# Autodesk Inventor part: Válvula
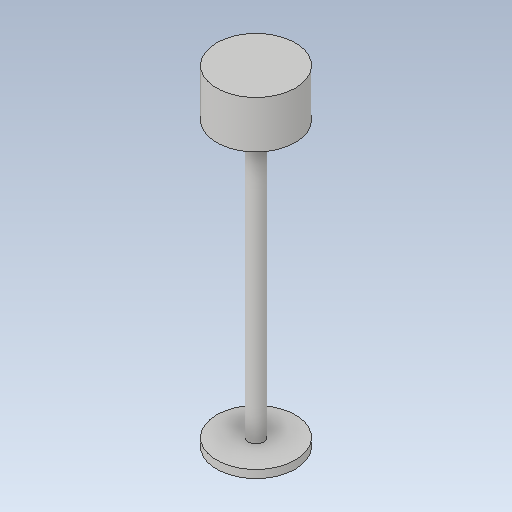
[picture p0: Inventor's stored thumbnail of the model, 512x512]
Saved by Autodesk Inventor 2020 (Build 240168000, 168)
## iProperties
Created: 2019-09
Part Number: Válvula
Material: Generic
Document SubType Name: Modeling
Designer: user
Density: 1 g/cm^3
Appearance: Default
Mass: 0.357356 g
Surface Area: 9.20487 cm^2
Volume: 0.357356 cm^3
Author: user
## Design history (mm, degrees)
sketch "Sketch1"
  geometry: C1 r 5 at (0, 0); 1 further point
  constraints: 1 centre point, 1 coincident
  dimensions: "d0" = 10 diameter of C1
extrude "Extrusion1" new body sketch "Sketch1" distance "d1" = 1; taper "d2" = 0 deg
sketch "Sketch2"
  geometry: C1 r 1 at (0, 0); 1 further point
  constraints: 1 centre point, 1 coincident
extrude "Extrusion2" join sketch "Sketch2" distance "d3" = 40; taper "d4" = 0 deg
sketch "Sketch3"
  geometry: C1 r 5 at (0, 0); 1 further point
  constraints: 1 centre point, 1 coincident
extrude "Extrusion3" join sketch "Sketch3" distance "d5" = 1; taper "d6" = 0 deg
sketch "Sketch4"
  geometry: C1 r 5 at (0, 0) reference; C2 r 5 at (0, 0); C3 r 1 at (0, 0) reference; C4 r 4.5 at (0, 0); 1 further point
  constraints: 2 centre point, 2 coincident
  dimensions: "d7" = 9 diameter of C4
extrude "Extrusion4" join sketch "Sketch4" distance "d8" = 5; taper "d9" = 0 deg
body "Solid1"
